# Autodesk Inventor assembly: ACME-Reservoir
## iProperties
Company: Autodesk, Inc.
Shininess: 64.0
Length Units: 11269
Angle Units: 11279
Time Units: 11290
Mass Units: 11283
Length Display Precision: 3
Angle Display Precision: 2
Compacted: True
Created: 2003-12
Part Number: ACME-Reservoir
Document SubType Name: Assembly
Catalog Web Link: www.autodesk.com
Vendor: Autodesk, Inc.
Designer: Administrator
Manufacturer: Standard
Standards Organization: Custom
Density: 0.0
Volumn: 0.0
Area: 0.0
PropertySet Name: Model Information
Control State: 0
Master: False
Checked Out: False
Author: Administrator
